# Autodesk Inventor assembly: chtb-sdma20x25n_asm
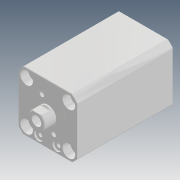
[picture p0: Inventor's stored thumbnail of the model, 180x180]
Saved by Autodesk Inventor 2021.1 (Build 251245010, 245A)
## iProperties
Created: 2018-05
Part Number: chtb-sdma20x25n_asm
Description: STEP AP214
Document SubType Name: Assembly
Designer: user
Title: chtb-sdma20x25n_asm.STEP
Revision Number: ÈÎºÎ
Sending System: SolidWorks 2016
Preprocessor: SwSTEP 2.0
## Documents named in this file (5)
- D:\Vault_2016\Projekty\Clamptek\Hydraulic\CHTB\CHTB-20\Inventor\CHTB-SDMA20x25N\chtb-sdma20x25n_asm.iam
- D:\Vault_2016\Projekty\Clamptek\Hydraulic\CHTB\CHTB-20\Inventor\CHTB-SDMA20x25N\CHTB-SDMA20X25NBT.ipt
- D:\Vault_2016\Projekty\Clamptek\Hydraulic\CHTB\CHTB-20\Inventor\CHTB-SDMA20x25N\CHTB-SDMA20X25NHSG.ipt
- D:\Vault_2016\Projekty\Clamptek\Hydraulic\CHTB\CHTB-20\Inventor\CHTB-SDMA20x25N\QG_3.ipt
- D:\Vault_2016\Projekty\Clamptek\Hydraulic\CHTB\CHTB-20\Inventor\CHTB-SDMA20x25N\socket set screw flat point_iso_ISO 4026 - M5 x 5-N.ipt
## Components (6 placed, 6 different names)
1. CHTB-SDMA20X25NBT_1
2. CHTB-SDMA20X25NHSG_2
3. QG_3_3
4. socket set screw flat point_iso_ISO 4026 - M5 x 5-N_4
5. socket set screw flat point_iso_ISO 4026 - M5 x 5-N_5
6. socket set screw flat point_iso_ISO 4026 - M5 x 5-N_6
